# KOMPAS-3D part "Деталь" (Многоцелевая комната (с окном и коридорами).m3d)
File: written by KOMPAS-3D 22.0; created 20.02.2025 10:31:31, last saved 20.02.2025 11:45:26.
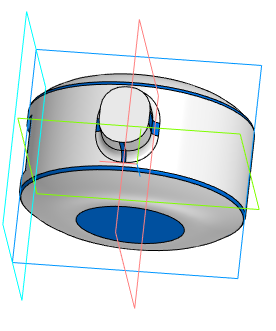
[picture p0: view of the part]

Document properties: Автор: Пользователь Windows; Полное имя файла: C:\Users\Student\Documents\Картошечка\База Сабнатика\Многоцелевая комната\Многоцелевая комната (с окном и коридорами).m3d

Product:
- Body: Тело 1
    Масса: 0.425402
- Part/product: Деталь
    Масса: 0.43308

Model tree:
1. Эскиз:3
2. Элемент вращения:1
     Угол 1 = 360
3. Скругление:1  (with: Элемент вращения:1)
     Радиус = 1
4. Смещенная плоскость:1
     Расстояние = 25
5. Эскиз:4
6. Элемент выдавливания:1
     Расстояние 2 = 2
7. Эскиз:5
8. Элемент выдавливания:2
     Расстояние 1 = 65
9. Скругление:3  (with: Элемент выдавливания:2)
     Радиус = 2
10. Скругление:4  (with: Элемент выдавливания:2)
     Радиус = 2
